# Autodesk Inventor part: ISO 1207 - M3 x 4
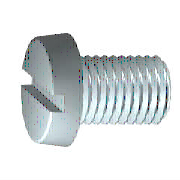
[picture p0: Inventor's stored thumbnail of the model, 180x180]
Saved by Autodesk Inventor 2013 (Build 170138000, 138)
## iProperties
Created: 2012-02
Part Number: ISO 1207 - M3 x 4
Material: Edelstahl, 440C
Description: Zylinderkopfschrauben mit Schlitz - Produktklasse A
Document SubType Name: Modeling
Standard: ISO 1207
Designer: rYan
Standard Revision: Third edition 1992-05-15
Standards Organization: ISO
Language: de-DE
Size Designation: M3 x 4
Categories: <MemberInstance><Categories><Category DisplayName="Verbindungselemente" InternalName="e4da775c-781d-43d5-af7c-5136215cf5a6" Mnemonic="FSTN"><Category DisplayNam
Density: 7.75 g/cm^3
IsCustomPart: 0
Author: rYan
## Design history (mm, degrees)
body "Solid1"
revolve "Körper" stored, may be unused: angle "d8" = 90 deg
sketch "Skizze2"
  geometry: L1 (0, 0)-(0, 2.575) reference; L2 (-2.75, 0.4)-(2.75, 0.4); L3 (2.75, 0.4)-(2.75, -0.4); L4 (2.75, -0.4)-(-2.75, -0.4); L5 (-2.75, -0.4)-(-2.75, 0.4); L6 (-2.75, 0)-(2.75, 0); L7 (0, 0.4)-(0, -0.4); C1 r 2.75 at (0, 0) reference; 1 further point
  constraints: 12 end point, 5 midpoint, 2 parallel, 1 collinear, 1 horizontal, 1 perpendicular
  dimensions: "d11" = 0.8 distance of L4.end L2.start (= SBR); "d12" = 5.5 distance of L2.start L2.end (= KOD)
fillet "Rundung1" dims "d14" = 0.1 (= RR)
extrude "Loch" cut sketch "Skizze2" distance "d19" = 0.85 (= STI); taper "d20" = 0 deg
feature "Gewinde" dims "d15" = 3 (= GEL), "d16" = 0
chamfer "Fase1" distance "d17" = 0.30673 (= -0.5 x SPD + 0.5 x GD); stored, may be unused: second distance "d18" = 0.30683 (computed from GUL), angle "d36" = 45 deg
workplane "Work Plane1"
sketch "Skizze1"
  geometry: L1 (-2, 0)-(4, 0); L2 (4, 0)-(4, 1.5); L3 (4, 1.5)-(1, 1.5); L4 (1, 1.5)-(0.693, 1.347); L5 (0.693, 1.347)-(0, 1.347); L6 (0, 1.347)-(0, 2.75); L7 (-3.2, 0)-(5.2, 0) reference; L8 (0, -0.55)-(0, 3.3) reference; L9 (-2, 0)-(-2, 2.575); L10 (0, 2.75)-(-2, 2.575); L11 (1, 1.5)-(0, 1.5)
  constraints: 18 end point, 4 parallel, 2 collinear, 2 perpendicular, 1 horizontal, 1 point on line
  dimensions: "d0" = 4 distance between parallel lines of L2 L6 (= NLG); "d1" = 3 distance from line of L3.end L2 (= GEL); "d2" = 0.30683 horizontal distance of L4.end L3.end (computed from GAL); "d3" = 2 distance from line of L1.start L6 (= KOH); "d4" = 3 diameter of L3 L1 (= GD); "d5" = 2.6935 diameter of L5 L1 (= BDM); "d9" = 5.5 diameter of L6.end L1 (= KOD); "d10" = 5 deg angle of L10 L1 (= KEWI)
other parameters: "GD" = 3 (= NND) [user parameter; used in 2 equation terms], "NLG" = 4 [user parameter; used in 1 equation term], "GEL" = 3 [user parameter; used in 2 equation terms], "KOD" = 5.5 [user parameter; used in 2 equation terms], "KOH" = 2 [user parameter; used in 1 equation term], "GAL" = 0.30673 (= 0.61345 x PTC) [user parameter; used in 1 equation term], "SPD" = 2.38655 (= NND - 1.2269 x PTC) [user parameter; used in 1 equation term], "BDM" = 2.6935 [user parameter; used in 1 equation term], "GUL" = 0.30673 (= 0.61345 x PTC) [user parameter; used in 1 equation term], "RR" = 0.1 [user parameter; used in 1 equation term], "d7" = 0, "SBR" = 0.8 [user parameter; used in 1 equation term], "STI" = 0.85 [user parameter; used in 1 equation term], "KEWI" = 5 deg [user parameter; used in 1 equation term], "d37" = 0, "d39" = 0, "PTC" = 0.5 [user parameter; used in 5 equation terms], "THREADDIA" = 3 [user parameter; used in 1 equation term], "TOA" = 30 deg [user parameter], "NND" = 3 [user parameter; used in 2 equation terms], "GD1" = 2.38655 (= THREADDIA - 1.2269 x PTC) [user parameter]
